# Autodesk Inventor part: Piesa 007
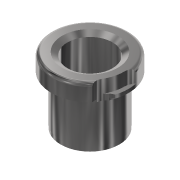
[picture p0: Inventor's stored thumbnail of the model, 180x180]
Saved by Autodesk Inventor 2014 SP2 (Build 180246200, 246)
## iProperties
Created: 2009-01
Part Number: Piesa 007
Document SubType Name: Modeling
Designer: Costel
Material: Steel
Density: 7.85 g/cm^3
Appearance: Steel - Polished
Author: Costel
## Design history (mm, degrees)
sketch "Sketch2"
  geometry: L1 (19, 53.402)-(19, 1); L2 (20, 0)-(24.3, 0); L3 (25, 4)-(25, 39.293); L4 (25.707, 40)-(30, 40); L5 (30, 40)-(30, 42); L6 (30, 42)-(32.5, 42); L7 (32.5, 42)-(32.5, 53); L8 (29.5, 56)-(23.5, 56); L9 (34.533, 0)-(14.764, 0) reference; L10 (0, -5.662)-(0, 73.608) reference; L11 (19, 53.402)-(23.5, 56); L12 (25, 39.293)-(24.293, 40); L13 (24.293, 40)-(25, 40.707); L14 (25, 40.707)-(25.707, 40); L15 (25, 4)-(24.8, 4); L16 (24.8, 4)-(24.8, 0.5); L17 (24.8, 0.5)-(24.3, 0); L18 (19, 1)-(20, 0); A1 r 3 centre (29.5, 53) between (32.5, 53) and (29.5, 56); 2 further points
  constraints: 32 end point, 8 parallel, 5 point on line, 4 perpendicular, 2 point on circle, 2 tangent, 1 centre point, 1 collinear, 1 vertical
  dimensions: "d0" = 56 distance between parallel lines of L9 L8; "d1" = 16 distance between parallel lines of L8 L4; "d2" = 2 distance between parallel lines of L4 L6; "d3" = 38 diameter of L1 L10; "d4" = 60 deg angle of L10 L11; "d5" = 47 diameter of L8.end L10; "d6" = 3 radius of A1; "d7" = 65 diameter of L7 L10; "d8" = 60 diameter of L5 L10; "d9" = 50 diameter of L3 L10; "d10" = 1 distance of L12.end L13.end; "d12" = 1 distance of L3.end L12.end; "d13" = 1 distance of L13.end L4.start; "d14" = 0.5 distance of L16.end point (24.8, 0); "d15" = 0.5 distance of L2.end point (24.8, 0) (= d14); "d16" = 4 distance between parallel lines of L2 L15; "d17" = 49.6 diameter of L16 L10; "d18" = 1 distance of L1.end point (19, 0); "d19" = 1 distance of L2.start point (19, 0) (= d18)
revolve "Revolution1" sketch "Sketch2" stored, may be unused: angle "d20" = 90 deg
sketch "Sketch3"
  geometry: L1 (-29, 61)-(-39.5, 61); L2 (-39.5, 61)-(-39.5, 45); L3 (-39.5, 45)-(-29, 45); L4 (-29, 45)-(-29, 61); L5 (0, 37.9)-(0, 67.3) reference; L6 (-25.707, 40)-(25.707, 40) reference; L7 (-30, 40)-(30, 40) reference
  constraints: 8 end point, 2 parallel, 1 horizontal, 1 perpendicular
  dimensions: "d21" = 39.5 distance between parallel lines of L5 L2; "d22" = 10.5 distance of L1.start L1.end; "d23" = 5 distance between parallel lines of L3 L7; "d24" = 16 distance of L1.end L2.end
  node "Projected Loop1"
revolve "Revolution2" stored, may be unused: angle "d25" = 30 deg
revolve "Revolution3" stored, may be unused: angle "d26" = 30 deg
sketch "Sketch5"
  geometry: L1 (10.5, -2)-(0, -2); L2 (0, -2)-(0, 18); L3 (0, 18)-(10.5, 18); L4 (10.5, 18)-(10.5, -2); L5 (-3.885, 0)-(-4.946, 0) reference; L6 (0.5, 0)-(-4.946, 0) reference; L7 (0.5, 0)-(0, 0) reference; L8 (0, 0)-(-3.885, 0) reference; L9 (-5.5, 0)-(-52.5, 0) reference; L10 (-29, 61.6)-(-29, -16.801) reference
  constraints: 8 end point, 2 parallel, 1 horizontal, 1 perpendicular
  dimensions: "d30" = 2 distance between parallel lines of L1 L6; "d31" = 20 distance of L3.end L1.start; "d32" = 39.5 distance between parallel lines of L10 L4; "d33" = 10.5 distance of L1.start L1.end
revolve "Revolution5" sketch "Sketch5" stored, may be unused: angle "d34" = 30 deg
body "Solid1"
node "Projected Loop3"
